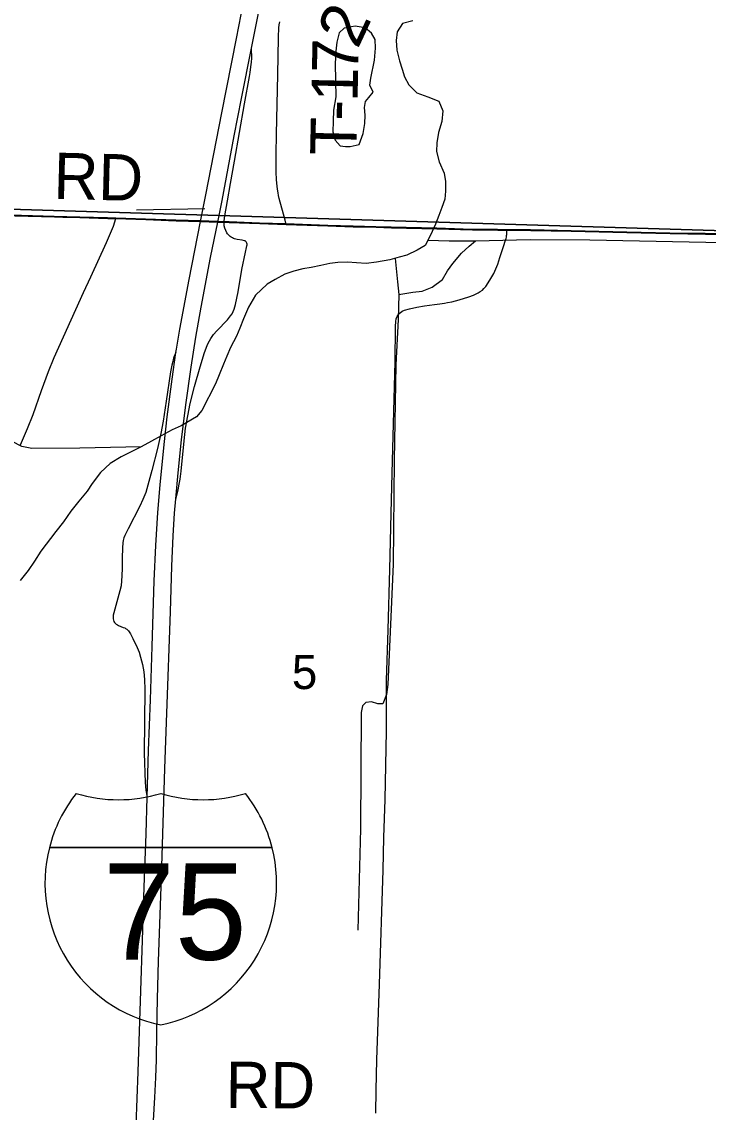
# Model space of a CAD drawing. Extents: x -59 to 43, y 0 to 22.
# Drawn here: x 26.258 to 27.1, y 14.155 to 15.494 of the extents above; entities that cross this region are included whole.
import ezdxf

# ---------------------------------------------------------------- set-up
doc = ezdxf.new("R2010")
doc.units = 0
for name, color, linetype in [('GM_X_Interchange_Ramps', 7, 'Continuous'), ('GM_X_Interstate_Location', 7, 'Continuous'), ('GM_X_Interstate_Route', 7, 'Continuous'), ('GM_X_Interstate_Shield', 7, 'Continuous'), ('GM_X_Major_River', 7, 'Continuous'), ('GM_X_Minor_Lake', 7, 'Continuous'), ('GM_X_Minor_River', 7, 'Continuous'), ('GM_X_Section', 7, 'Continuous'), ('GM_X_Section_Text', 7, 'Continuous'), ('GM_X_Township_Road', 7, 'Continuous'), ('GM_X_Township_Road_Text', 7, 'Continuous')]:
    doc.layers.add(name, color=color, linetype=linetype)

msp = doc.modelspace()

# ---------------------------------------------------------------- linework, layer by layer
at = {"layer": 'GM_X_Interchange_Ramps'}
for points in [[(26.5064, 15.2479), (26.5065, 15.2497), (26.5073, 15.2558), (26.5107, 15.2741), (26.5145, 15.2954), (26.5194, 15.3229), (26.5316, 15.3932), (26.5376, 15.4267), (26.5385, 15.4316), (26.5394, 15.4386), (26.54, 15.4445), (26.5403, 15.4494), (26.5402, 15.4616)], [(26.2174, 15.2572), (26.2982, 15.2549), (26.3293, 15.2542), (26.3635, 15.2532), (26.3736, 15.2529), (26.4101, 15.2517), (26.4473, 15.2503), (26.4774, 15.2495), (26.4984, 15.2487), (26.5061, 15.2484), (26.5126, 15.2483), (26.5499, 15.2468), (26.5824, 15.2457), (26.6337, 15.244), (26.6648, 15.2428), (26.6927, 15.2421), (26.7673, 15.2404), (26.8108, 15.2391), (26.8419, 15.2388), (26.8533, 15.2386), (26.8823, 15.2383), (26.9321, 15.2372), (27.0005, 15.2357), (27.0533, 15.2346), (27.0968, 15.2338), (27.131, 15.233)], [(27.131, 15.233), (27.0968, 15.2338), (27.0533, 15.2346), (27.0005, 15.2357), (26.9321, 15.2372), (26.8823, 15.2383), (26.8533, 15.2386), (26.8419, 15.2388), (26.8108, 15.2391), (26.7673, 15.2404), (26.6927, 15.2421), (26.6648, 15.2428), (26.6337, 15.244), (26.5824, 15.2457), (26.5499, 15.2468), (26.5126, 15.2483), (26.5061, 15.2484), (26.4984, 15.2487), (26.4774, 15.2495), (26.4473, 15.2503), (26.4101, 15.2517), (26.3736, 15.2529), (26.3635, 15.2532), (26.3293, 15.2542), (26.2982, 15.2549), (26.2174, 15.2572)], [(26.4472, 14.9082), (26.4501, 14.9193), (26.4514, 14.9262), (26.4525, 14.9325), (26.4536, 14.9424), (26.4573, 14.9794), (26.4593, 14.9948), (26.4619, 15.0101), (26.465, 15.0253), (26.4703, 15.0463), (26.477, 15.0702), (26.4825, 15.088), (26.4858, 15.0967), (26.487, 15.0995), (26.49, 15.105), (26.4935, 15.11), (26.4975, 15.1147), (26.5105, 15.1282), (26.5145, 15.1329), (26.5162, 15.1355), (26.5177, 15.1382), (26.5188, 15.141), (26.5206, 15.147), (26.5236, 15.1622), (26.5283, 15.1897), (26.5326, 15.211), (26.5341, 15.217), (26.5344, 15.2188), (26.5346, 15.2201), (26.5346, 15.221), (26.5343, 15.2221), (26.5339, 15.223), (26.5335, 15.2237), (26.5329, 15.2244), (26.5324, 15.2249), (26.5316, 15.2252), (26.5286, 15.2258), (26.5224, 15.2267), (26.5194, 15.2274), (26.5179, 15.228), (26.5166, 15.2286), (26.5152, 15.2294), (26.514, 15.2303), (26.5129, 15.2312), (26.5117, 15.2324), (26.5108, 15.2334), (26.5098, 15.2348), (26.5084, 15.2376), (26.5073, 15.2405), (26.5067, 15.2435), (26.5064, 15.2457), (26.5064, 15.2479)], [(26.4474, 15.0879), (26.446, 15.085), (26.4452, 15.0833), (26.4444, 15.0808), (26.4434, 15.077), (26.4423, 15.0723), (26.4406, 15.0642), (26.4353, 15.0283), (26.4316, 15.0037), (26.4289, 14.9884), (26.4248, 14.9702), (26.418, 14.9431), (26.4131, 14.9251), (26.4103, 14.9162), (26.4069, 14.9075), (26.403, 14.8991), (26.3887, 14.8714), (26.3845, 14.8631), (26.3834, 14.8602), (26.3826, 14.8572), (26.3821, 14.8541), (26.3818, 14.8479), (26.3816, 14.8355), (26.3813, 14.823), (26.3811, 14.8138), (26.3808, 14.8076), (26.38, 14.8015), (26.3786, 14.7954), (26.371, 14.7684), (26.3704, 14.7654), (26.3702, 14.7623), (26.3704, 14.7609), (26.3707, 14.7592), (26.3713, 14.7578), (26.3721, 14.7565), (26.3731, 14.7553), (26.3742, 14.7543), (26.3756, 14.7534), (26.3768, 14.7526), (26.3827, 14.7504), (26.3845, 14.7497), (26.3855, 14.7491), (26.387, 14.7481), (26.388, 14.7473), (26.3892, 14.746), (26.39, 14.745), (26.3918, 14.7425), (26.3947, 14.7369), (26.3999, 14.7256), (26.4021, 14.7198), (26.4041, 14.7139), (26.4064, 14.7049), (26.408, 14.6957), (26.4088, 14.6864), (26.4092, 14.674), (26.4086, 14.5962), (26.4096, 14.5599), (26.4106, 14.5504), (26.4122, 14.5421)]]:
    msp.add_lwpolyline(points, dxfattribs=at)
at = {"layer": 'GM_X_Interstate_Route'}
for points in [[(26.4474, 15.0879), (26.448, 15.092), (26.4521, 15.1165), (26.4637, 15.1776), (26.4776, 15.2489), (26.4839, 15.2813), (26.5036, 15.382), (26.5215, 15.4735), (26.5301, 15.5175)], [(26.5402, 15.4616), (26.5456, 15.4882), (26.551, 15.5166)], [(26.4197, 14.1452), (26.4214, 14.1731), (26.4228, 14.1979), (26.4236, 14.2197), (26.4241, 14.2538), (26.4246, 14.2942), (26.426, 14.3408), (26.4295, 14.4434), (26.4338, 14.577), (26.4363, 14.6453), (26.4406, 14.7696), (26.4422, 14.8255), (26.4439, 14.8628), (26.4457, 14.8907), (26.4472, 14.9082), (26.45, 14.9403), (26.4542, 14.9805), (26.4594, 15.0237), (26.4659, 15.0699), (26.4717, 15.1068), (26.4782, 15.1435), (26.4899, 15.2046), (26.4986, 15.2481), (26.5039, 15.2747), (26.5189, 15.3541), (26.5278, 15.3999), (26.5402, 15.4616)], [(26.3975, 14.1), (26.3977, 14.1054), (26.3988, 14.1393), (26.4011, 14.2048), (26.4042, 14.3043), (26.4065, 14.3664), (26.4085, 14.4316), (26.4109, 14.4969), (26.4122, 14.5421), (26.4139, 14.5994), (26.4163, 14.6615), (26.4182, 14.7268), (26.4208, 14.8076), (26.4228, 14.851), (26.4252, 14.8914), (26.4279, 14.9254), (26.4328, 14.9749), (26.4367, 15.0089), (26.4427, 15.0551), (26.4474, 15.0879)]]:
    msp.add_lwpolyline(points, dxfattribs=at)
at = {"layer": 'GM_X_Interstate_Shield'}
for p, q in [((26.2921, 14.48), (26.5654, 14.48)), ((26.5654, 14.48), (26.2921, 14.48)), ((26.5654, 14.48), (26.2921, 14.48))]:
    msp.add_line(p, q, dxfattribs=at)
for centre, start, end in [((26.4643, 14.4364), 141.669, 165.8066), ((26.3769, 14.7164), 253.0091, 286.9909), ((26.4807, 14.7164), 253.0091, 286.9909), ((26.3933, 14.4364), 14.1934, 38.331), ((26.4643, 14.4364), 165.8066, 258.463), ((26.3933, 14.4364), 281.537, 14.1934)]:
    msp.add_arc(centre, 0.1776, start, end, dxfattribs=at)
at = {"layer": 'GM_X_Major_River'}
for points in [[(26.7382, 15.4951), (26.7253, 15.4919), (26.7186, 15.4814), (26.7177, 15.4708), (26.7182, 15.459), (26.7218, 15.446), (26.725, 15.4357), (26.7279, 15.4262), (26.733, 15.4166), (26.7431, 15.4069), (26.7563, 15.4017), (26.7699, 15.3965), (26.775, 15.3847), (26.7736, 15.3714), (26.7696, 15.3578), (26.7675, 15.3453), (26.7669, 15.3347), (26.7705, 15.3221), (26.7763, 15.3079), (26.778, 15.298), (26.7782, 15.2859), (26.7772, 15.276), (26.7736, 15.2658), (26.77, 15.256), (26.7657, 15.2454), (26.7597, 15.2319), (26.753, 15.2191), (26.7434, 15.2135), (26.7308, 15.2073), (26.7212, 15.2048), (26.7098, 15.2016), (26.6934, 15.1989), (26.6808, 15.1972), (26.6687, 15.1978), (26.6577, 15.1987), (26.6459, 15.1986), (26.636, 15.1972), (26.6253, 15.1948), (26.6131, 15.1923), (26.6032, 15.1906), (26.5921, 15.1878), (26.581, 15.1842), (26.5691, 15.1775), (26.5595, 15.172), (26.5448, 15.1582), (26.5362, 15.1436), (26.5302, 15.1292), (26.5259, 15.1179), (26.5215, 15.1081), (26.5144, 15.0942), (26.5097, 15.0832), (26.5057, 15.0734), (26.5005, 15.0606), (26.4961, 15.0493), (26.4792, 15.0167)], [(26.4792, 15.0167), (26.4728, 15.0091), (26.4539, 14.9979), (26.4426, 14.9929), (26.4292, 14.9854), (26.4175, 14.979), (26.4049, 14.9722), (26.3931, 14.9665), (26.3802, 14.9597), (26.3665, 14.9518), (26.3547, 14.9404), (26.3445, 14.9272), (26.3384, 14.9177), (26.3281, 14.9052), (26.3186, 14.8931), (26.3094, 14.8802), (26.2999, 14.868), (26.2816, 14.8438), (26.274, 14.8316), (26.266, 14.8203), (26.2561, 14.8078)]]:
    msp.add_lwpolyline(points, dxfattribs=at)
at = {"layer": 'GM_X_Minor_Lake'}
msp.add_line((26.6427, 15.4425), (26.6435, 15.4018), dxfattribs=at)
msp.add_lwpolyline([(26.6435, 15.4018), (26.6405, 15.3856), (26.6403, 15.3719), (26.64, 15.359), (26.6429, 15.3487), (26.6488, 15.3417), (26.6553, 15.3409), (26.661, 15.3408), (26.672, 15.3432), (26.6772, 15.3568), (26.679, 15.3689), (26.6795, 15.3792), (26.6786, 15.3887), (26.6798, 15.3959), (26.6841, 15.4011), (26.6892, 15.4075), (26.6851, 15.4163), (26.6864, 15.4246), (26.691, 15.4466), (26.6924, 15.4614), (26.6918, 15.472), (26.6871, 15.4801), (26.6796, 15.4867), (26.6674, 15.4884), (26.6537, 15.486), (26.6475, 15.4804), (26.6447, 15.4687), (26.6437, 15.4577), (26.6427, 15.4425)], dxfattribs=at)
at = {"layer": 'GM_X_Minor_River'}
for points in [[(26.4828, 15.2641), (26.399, 15.2628)], [(26.7208, 15.1592), (26.7379, 15.162), (26.7494, 15.1633), (26.7616, 15.168), (26.7743, 15.1777), (26.7806, 15.1882), (26.7872, 15.1972), (26.7977, 15.2099), (26.807, 15.2185), (26.8147, 15.2248)], [(26.7566, 15.2259), (26.7824, 15.225), (26.8147, 15.2248), (26.882, 15.2266), (26.955, 15.2261), (27.1381, 15.2224), (27.2182, 15.2202), (27.3246, 15.2176), (27.4291, 15.2168), (27.4606, 15.2151)], [(26.7162, 15.2034), (26.7192, 15.1745), (26.7208, 15.1592), (26.7202, 15.1285), (26.7173, 15.0727), (26.7152, 14.9557), (26.7137, 14.8281), (26.7072, 14.6801), (26.7055, 14.668), (26.7011, 14.6566), (26.695, 14.6564), (26.6871, 14.6592), (26.6802, 14.6582), (26.6764, 14.654), (26.6747, 14.6461), (26.6736, 14.5033), (26.6706, 14.3788)], [(26.4049, 14.9722), (26.3294, 14.9705), (26.2706, 14.9699), (26.2585, 14.9726), (26.2463, 14.9787)]]:
    msp.add_lwpolyline(points, dxfattribs=at)
at = {"layer": 'GM_X_Section'}
for points in [[(26.2361, 16.2622), (27.2374, 16.2454), (27.2021, 15.2348), (26.2022, 15.2649), (26.1685, 15.2661)], [(26.2022, 15.2649), (27.2021, 15.2348), (27.2112, 15.2343), (27.188, 14.1311), (26.1894, 14.1445)]]:
    msp.add_lwpolyline(points, close=True, dxfattribs=at)
at = {"layer": 'GM_X_Township_Road'}
for points in [[(26.5827, 15.2451), (26.5813, 15.2504), (26.5742, 15.2768), (26.5734, 15.2805), (26.5726, 15.2841), (26.5719, 15.2886), (26.5714, 15.2921), (26.571, 15.2959), (26.5707, 15.3001), (26.5703, 15.3094), (26.5704, 15.3312), (26.5709, 15.356), (26.5724, 15.4294), (26.5729, 15.4518), (26.573, 15.4741), (26.5732, 15.4786), (26.5735, 15.4828), (26.5738, 15.4865), (26.5742, 15.4903), (26.5748, 15.494)], [(25.9564, 15.2659), (25.9598, 15.2657), (26.0219, 15.2638), (26.0686, 15.2622), (26.0934, 15.2611), (26.112, 15.2604), (26.1369, 15.2596), (26.1524, 15.2591), (26.2176, 15.2567), (26.2984, 15.2544), (26.3085, 15.2542)], [(26.3085, 15.2542), (26.3295, 15.2537), (26.3637, 15.2526), (26.3738, 15.2523)], [(26.3341, 15.1617), (26.3428, 15.1807), (26.3623, 15.2231), (26.3685, 15.2373), (26.3706, 15.2431), (26.3738, 15.2523)], [(26.3738, 15.2523), (26.4103, 15.2512), (26.4476, 15.2497), (26.4776, 15.2489), (26.4986, 15.2481), (26.5064, 15.2479), (26.5128, 15.2477), (26.5501, 15.2462), (26.5827, 15.2451)], [(26.5827, 15.2451), (26.6339, 15.2434), (26.665, 15.2422), (26.693, 15.2416), (26.7119, 15.2411)], [(26.6925, 14.1542), (26.6931, 14.1821), (26.694, 14.2194), (26.697, 14.3125), (26.7014, 14.4522), (26.7026, 14.4926), (26.704, 14.5392), (26.7057, 14.623), (26.7056, 14.651), (26.7058, 14.6852), (26.7076, 14.7473), (26.7098, 14.8218), (26.7116, 14.8901), (26.7128, 14.9398), (26.7165, 15.0764), (26.7167, 15.1199), (26.7171, 15.1261), (26.7176, 15.1292), (26.7186, 15.1321), (26.7203, 15.1347), (26.7225, 15.1368), (26.7251, 15.1385), (26.7279, 15.1398), (26.7339, 15.1417), (26.7429, 15.1436), (26.7522, 15.145), (26.7644, 15.1468), (26.771, 15.1476), (26.7767, 15.1485), (26.7805, 15.1491), (26.7859, 15.1501), (26.7949, 15.1524), (26.8068, 15.1561), (26.8126, 15.1583), (26.8182, 15.161), (26.8208, 15.1626), (26.8233, 15.1645), (26.8253, 15.1666), (26.8274, 15.1691), (26.8326, 15.1769), (26.8372, 15.185), (26.8399, 15.1906), (26.8421, 15.1964), (26.8448, 15.2045), (26.8493, 15.218), (26.8518, 15.226), (26.8524, 15.228), (26.8528, 15.2297), (26.853, 15.2314), (26.8532, 15.2327), (26.8535, 15.2381)], [(26.7119, 15.2411), (26.7676, 15.2399), (26.8111, 15.2385), (26.8421, 15.2382), (26.8535, 15.2381)], [(26.8535, 15.2381), (26.8826, 15.2378), (26.9323, 15.2367), (27.0007, 15.2352), (27.0535, 15.2341), (27.097, 15.2332), (27.1312, 15.2324), (27.1623, 15.2317), (27.1965, 15.2309), (27.2173, 15.2306)], [(26.2566, 14.9746), (26.2654, 14.9945), (26.2721, 15.0118), (26.2824, 15.0411), (26.2911, 15.0644), (26.298, 15.0817), (26.3093, 15.1073), (26.3341, 15.1617)]]:
    msp.add_lwpolyline(points, dxfattribs=at)

# ---------------------------------------------------------------- texts
at = {"layer": 'GM_X_Interstate_Location'}
for s in ['.', '-', ',']:
    msp.add_text(s, height=0.000189, dxfattribs=at).set_placement((26.4287, 14.4044))
msp.add_text('75', height=0.000189, rotation=0, dxfattribs=at).set_placement((26.3901, 14.3652))
at = {"layer": 'GM_X_Interstate_Shield'}
msp.add_text('75', height=0.11837, dxfattribs=at).set_placement((26.3581, 14.3424))
at = {"layer": 'GM_X_Section_Text'}
msp.add_text('5', height=0.0419, rotation=0, dxfattribs=at).set_placement((26.5896, 14.6747))
at = {"layer": 'GM_X_Township_Road_Text'}
for s, height, rotation, p in [('2', 0.0568, 65.0293, (26.6702, 15.4594)), ('7', 0.0568, 88.7607, (26.6709, 15.4304)), ('1', 0.0568, 88.7521, (26.6701, 15.3954)), ('-', 0.0568, 88.7431, (26.6696, 15.3721)), ('T', 0.0568, 88.7485, (26.6687, 15.3296)), ('RD', 0.05682, 358.5255, (26.2967, 15.2766)), ('RD', 0.05682, 359.5061, (26.5082, 14.1606))]:
    msp.add_text(s, height=height, rotation=rotation, dxfattribs=at).set_placement(p)

doc.saveas('drawing.dxf')
